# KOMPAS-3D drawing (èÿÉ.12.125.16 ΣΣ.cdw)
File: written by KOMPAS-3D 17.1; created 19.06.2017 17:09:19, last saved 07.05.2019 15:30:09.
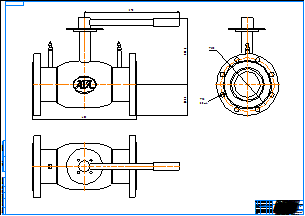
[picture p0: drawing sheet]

Sheet 1: A0, landscape

Title block, sheet 1: name: КШР.12.125.16 фф; material: Внимание! Данный продукт является объектом авторского права ООО «Торговый Дом АДЛ». / Запрещается изменение, копирование, распространение / (в том числе путем копирования на другие сайты и ресурсы в Интернете) / или любое иное использование информации и объектов без предварительного / согласия правообладателя (ООО «Торговый Дом АДЛ»).; scale: 1:1; sheets: 1; organisation: ООО "Торговый дом АДЛ"; sheet format: A0; stored path: C:\Users\tra\Desktop\2д чертежи\Шаровые краны БИВАЛ\КШР_Бивал_серия_12\KOMPAS 2D\КШР.12.125.16 фф.cdw

Views: Спереди 1, Проекционный вид 2, Проекционный вид 3
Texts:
  Klimkovich
  ADL
Dimensions and other numbers on the sheet: 405; 370; 258,4; 122,5; 210; 18; 8 Отв.; 1:1; 1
